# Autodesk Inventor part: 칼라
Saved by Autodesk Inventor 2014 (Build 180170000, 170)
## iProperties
Created: 2026-05
Part Number: 칼라
Material: 강철, 연강
Document SubType Name: Modeling
Designer: dg
Density: 7.86 g/cm^3
Appearance: 강철
Mass: 74.0788 g
Surface Area: 52.143 cm^2
Volume: 9.42478 cm^3
Author: jhkim
Creation Date: 2026-04-23
Sending System: Autodesk Inventor 2027
Preprocessor: ST-DEVELOPER v20.1
Author: dg
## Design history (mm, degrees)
node "칼라1"
node "솔리드1"
node "기준1"
